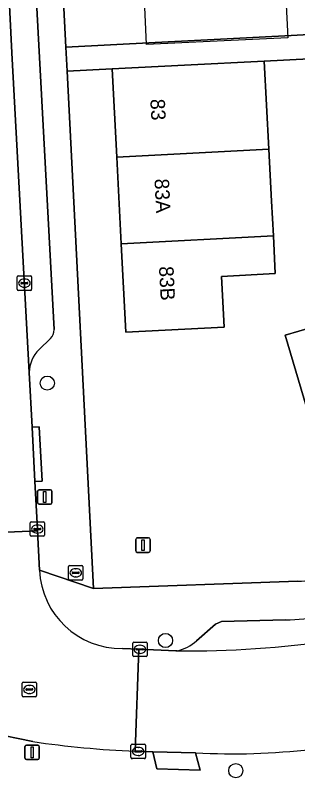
# Model space of a CAD drawing. Extents: x 158086 to 159499, y 382904 to 383981.
# Drawn here: x 158897.5 to 158917, y 383352.1 to 383404.7 of the extents above; entities that cross this region are included whole.
import ezdxf

# ---------------------------------------------------------------- set-up
doc = ezdxf.new("R2010")
doc.units = 0
for name, color, linetype in [('IMGEO_Boom', 7, 'Continuous'), ('IMGEO_Brandkraan', 7, 'Continuous'), ('IMGEO_Erf', 7, 'Continuous'), ('IMGEO_Kolk', 7, 'Continuous'), ('IMGEO_Lichtmast', 7, 'Continuous'), ('IMGEO_Pand', 7, 'Continuous'), ('IMGEO_Pand_nummerreeks', 7, 'Continuous'), ('IMGEO_Pand_vergunning_verleend', 7, 'Continuous'), ('IMGEO_Parkeervlak_open', 7, 'Continuous'), ('IMGEO_Rijbaan_lokaal_open', 7, 'Continuous'), ('IMGEO_Rioolput', 7, 'Continuous'), ('IMGEO_Voetpad_open', 7, 'Continuous')]:
    doc.layers.add(name, color=color, linetype=linetype)

msp = doc.modelspace()

# ---------------------------------------------------------------- linework, layer by layer
at = {"layer": 'IMGEO_Boom'}
for centre in [(158899.692, 383379.334), (158907.858, 383361.557), (158912.717, 383352.566)]:
    msp.add_circle(centre, 0.489, dxfattribs=at)
at = {"layer": 'IMGEO_Brandkraan'}
for p, q in [((158901.156, 383365.806), (158901.156, 383366.658)), ((158901.231, 383366.732), (158902.083, 383366.732)), ((158901.644, 383366.512), (158901.669, 383366.512)), ((158902.157, 383366.658), (158902.157, 383365.806)), ((158901.415, 383366.226), (158901.415, 383366.238)), ((158901.853, 383366.189), (158901.455, 383366.189)), ((158901.458, 383366.275), (158901.856, 383366.275)), ((158901.667, 383365.952), (158901.642, 383365.952)), ((158901.899, 383366.238), (158901.899, 383366.226)), ((158902.083, 383365.732), (158901.231, 383365.732))]:
    msp.add_line(p, q, dxfattribs=at)
for points in [[(158901.156, 383365.806), (158901.156, 383366.658)], [(158901.231, 383366.732), (158902.083, 383366.732)], [(158902.157, 383366.658), (158902.157, 383365.806)], [(158902.083, 383365.732), (158901.231, 383365.732)]]:
    msp.add_lwpolyline(points, dxfattribs=at)
for centre, radius, start, end in [((158901.233, 383366.656), 0.0765, 91.552, 178.448), ((158901.233, 383366.656), 0.0765, 91.552, 178.448), ((158902.081, 383366.656), 0.0765, 1.552, 88.448), ((158902.081, 383366.656), 0.0765, 1.552, 88.448), ((158901.455, 383366.235), 0.0403, 85.8775, 175.7526), ((158901.452, 383366.225), 0.0366, 178.938, 274.7102), ((158901.856, 383366.232), 0.043, 264.8664, 352.4533), ((158901.86, 383366.237), 0.0386, 1.7309, 96.639), ((158901.233, 383365.808), 0.0765, 181.552, 268.448), ((158901.233, 383365.808), 0.0765, 181.552, 268.448), ((158902.081, 383365.808), 0.0765, 271.552, 358.448), ((158902.081, 383365.808), 0.0765, 271.552, 358.448)]:
    msp.add_arc(centre, radius, start, end, dxfattribs=at)
for centre, major_axis, ratio, start_param, end_param in [((158901.643, 383366.232), (-0.387, 0.002), 0.722429, 4.712389, 7.853982), ((158901.668, 383366.232), (-0.39, 0.002), 0.717154, 1.570796, 4.712389)]:
    msp.add_ellipse(centre, major_axis=major_axis, ratio=ratio, start_param=start_param, end_param=end_param, dxfattribs=at)
at = {"layer": 'IMGEO_Erf'}
for points in [[(158898.201, 383456.346), (158900.97, 383402.538), (158907.136, 383402.855), (158912.13, 383403.115), (158916.543, 383403.344), (158918.608, 383403.452), (158918.596, 383403.675), (158929.519, 383404.297), (158929.403, 383404.042), (158934.745, 383404.327), (158936.388, 383404.415), (158935.294, 383408.293)], [(158921.657, 383386.888), (158922.254, 383388.21), (158922.499, 383388.752), (158920.79, 383389.524), (158921.396, 383390.834), (158918.923, 383391.978), (158920.68, 383395.777), (158922.416, 383399.528), (158924.889, 383398.384), (158926.654, 383402.198), (158914.688, 383401.579), (158915.004, 383395.482), (158915.19, 383391.89), (158915.313, 383389.503), (158915.448, 383386.896), (158911.73, 383386.703), (158911.912, 383383.192), (158905.119, 383382.841), (158904.802, 383388.957), (158904.493, 383394.936), (158904.177, 383401.035), (158901.056, 383400.874), (158902.894, 383365.138), (158916.998, 383365.647)], [(158920.898, 383366.383), (158919.749, 383370.262), (158919.247, 383370.113), (158919.167, 383370.382), (158919.671, 383370.531), (158919.007, 383372.772), (158918.485, 383372.617), (158918.393, 383372.93), (158918.956, 383373.097), (158916.131, 383382.636), (158919.916, 383383.757), (158921.657, 383386.888)]]:
    msp.add_lwpolyline(points, dxfattribs=at)
msp.add_arc((158916.222, 383380.457), 14.831, 272.9974, 288.3767, dxfattribs=at)
at = {"layer": 'IMGEO_Kolk'}
for p, q in [((158897.61, 383385.812), (158897.61, 383386.664)), ((158897.685, 383386.738), (158898.537, 383386.738)), ((158898.098, 383386.518), (158898.123, 383386.518)), ((158898.611, 383386.664), (158898.611, 383385.812)), ((158897.869, 383386.232), (158897.869, 383386.244)), ((158898.307, 383386.195), (158897.909, 383386.195)), ((158897.912, 383386.281), (158898.31, 383386.281)), ((158898.121, 383385.958), (158898.096, 383385.958)), ((158898.353, 383386.244), (158898.353, 383386.232)), ((158898.537, 383385.738), (158897.685, 383385.738)), ((158898.505, 383368.826), (158898.505, 383369.678)), ((158898.58, 383369.752), (158899.432, 383369.752)), ((158899.506, 383369.678), (158899.506, 383368.826)), ((158898.764, 383369.246), (158898.764, 383369.258)), ((158899.202, 383369.209), (158898.804, 383369.209)), ((158898.807, 383369.295), (158899.205, 383369.295)), ((158898.993, 383369.532), (158899.018, 383369.532)), ((158899.248, 383369.258), (158899.248, 383369.246)), ((158899.432, 383368.752), (158898.58, 383368.752)), ((158899.016, 383368.972), (158898.991, 383368.972)), ((158905.593, 383360.519), (158905.593, 383361.371)), ((158905.668, 383361.445), (158906.52, 383361.445)), ((158906.081, 383361.225), (158906.106, 383361.225)), ((158906.594, 383361.371), (158906.594, 383360.519)), ((158905.852, 383360.939), (158905.852, 383360.951)), ((158906.29, 383360.902), (158905.892, 383360.902)), ((158905.895, 383360.988), (158906.293, 383360.988)), ((158906.104, 383360.665), (158906.079, 383360.665)), ((158906.336, 383360.951), (158906.336, 383360.939)), ((158906.52, 383360.445), (158905.668, 383360.445)), ((158905.475, 383353.469), (158905.475, 383354.321)), ((158905.55, 383354.395), (158906.402, 383354.395)), ((158906.476, 383354.321), (158906.476, 383353.469)), ((158905.734, 383353.889), (158905.734, 383353.901)), ((158906.172, 383353.852), (158905.774, 383353.852)), ((158905.777, 383353.938), (158906.175, 383353.938)), ((158905.963, 383354.175), (158905.988, 383354.175)), ((158906.218, 383353.901), (158906.218, 383353.889)), ((158906.402, 383353.395), (158905.55, 383353.395)), ((158905.986, 383353.615), (158905.961, 383353.615))]:
    msp.add_line(p, q, dxfattribs=at)
for points in [[(158897.61, 383385.812), (158897.61, 383386.664)], [(158897.685, 383386.738), (158898.537, 383386.738)], [(158898.611, 383386.664), (158898.611, 383385.812)], [(158898.537, 383385.738), (158897.685, 383385.738)], [(158898.505, 383368.826), (158898.505, 383369.678)], [(158898.58, 383369.752), (158899.432, 383369.752)], [(158899.506, 383369.678), (158899.506, 383368.826)], [(158899.432, 383368.752), (158898.58, 383368.752)], [(158905.593, 383360.519), (158905.593, 383361.371)], [(158905.668, 383361.445), (158906.52, 383361.445)], [(158906.594, 383361.371), (158906.594, 383360.519)], [(158906.52, 383360.445), (158905.668, 383360.445)], [(158905.475, 383353.469), (158905.475, 383354.321)], [(158905.55, 383354.395), (158906.402, 383354.395)], [(158906.476, 383354.321), (158906.476, 383353.469)], [(158906.402, 383353.395), (158905.55, 383353.395)]]:
    msp.add_lwpolyline(points, dxfattribs=at)
for centre, radius, start, end in [((158897.687, 383386.662), 0.0765, 91.552, 178.448), ((158897.687, 383386.662), 0.0765, 91.552, 178.448), ((158898.535, 383386.662), 0.0765, 1.552, 88.448), ((158898.535, 383386.662), 0.0765, 1.552, 88.448), ((158897.909, 383386.241), 0.0403, 85.8775, 175.7526), ((158897.906, 383386.231), 0.0366, 178.938, 274.7102), ((158898.31, 383386.238), 0.043, 264.8664, 352.4533), ((158898.314, 383386.243), 0.0386, 1.7309, 96.639), ((158897.687, 383385.814), 0.0765, 181.552, 268.448), ((158897.687, 383385.814), 0.0765, 181.552, 268.448), ((158898.535, 383385.814), 0.0765, 271.552, 358.448), ((158898.535, 383385.814), 0.0765, 271.552, 358.448), ((158898.582, 383369.676), 0.0765, 91.552, 178.448), ((158898.582, 383369.676), 0.0765, 91.552, 178.448), ((158899.43, 383369.676), 0.0765, 1.552, 88.448), ((158899.43, 383369.676), 0.0765, 1.552, 88.448), ((158898.804, 383369.255), 0.0403, 85.8775, 175.7526), ((158898.801, 383369.245), 0.0366, 178.938, 274.7102), ((158899.205, 383369.252), 0.043, 264.8664, 352.4533), ((158899.209, 383369.257), 0.0386, 1.7309, 96.639), ((158898.582, 383368.828), 0.0765, 181.552, 268.448), ((158898.582, 383368.828), 0.0765, 181.552, 268.448), ((158899.43, 383368.828), 0.0765, 271.552, 358.448), ((158899.43, 383368.828), 0.0765, 271.552, 358.448), ((158905.67, 383361.369), 0.0765, 91.552, 178.448), ((158905.67, 383361.369), 0.0765, 91.552, 178.448), ((158906.518, 383361.369), 0.0765, 1.552, 88.448), ((158906.518, 383361.369), 0.0765, 1.552, 88.448), ((158905.892, 383360.948), 0.0403, 85.8775, 175.7526), ((158905.889, 383360.938), 0.0366, 178.938, 274.7102), ((158906.293, 383360.945), 0.043, 264.8664, 352.4533), ((158906.297, 383360.95), 0.0386, 1.7309, 96.639), ((158905.67, 383360.521), 0.0765, 181.552, 268.448), ((158905.67, 383360.521), 0.0765, 181.552, 268.448), ((158906.518, 383360.521), 0.0765, 271.552, 358.448), ((158906.518, 383360.521), 0.0765, 271.552, 358.448), ((158905.552, 383354.319), 0.0765, 91.552, 178.448), ((158905.552, 383354.319), 0.0765, 91.552, 178.448), ((158906.4, 383354.319), 0.0765, 1.552, 88.448), ((158906.4, 383354.319), 0.0765, 1.552, 88.448), ((158905.774, 383353.898), 0.0403, 85.8775, 175.7526), ((158905.771, 383353.888), 0.0366, 178.938, 274.7102), ((158906.175, 383353.895), 0.043, 264.8664, 352.4533), ((158906.179, 383353.9), 0.0386, 1.7309, 96.639), ((158905.552, 383353.471), 0.0765, 181.552, 268.448), ((158905.552, 383353.471), 0.0765, 181.552, 268.448), ((158906.4, 383353.471), 0.0765, 271.552, 358.448), ((158906.4, 383353.471), 0.0765, 271.552, 358.448)]:
    msp.add_arc(centre, radius, start, end, dxfattribs=at)
for centre, major_axis, ratio, start_param, end_param in [((158898.097, 383386.238), (-0.387, 0.002), 0.722429, 4.712389, 7.853982), ((158898.122, 383386.238), (-0.39, 0.002), 0.717154, 1.570796, 4.712389), ((158898.992, 383369.252), (-0.387, 0.002), 0.722429, 4.712389, 7.853982), ((158899.017, 383369.252), (-0.39, 0.002), 0.717154, 1.570796, 4.712389), ((158906.08, 383360.945), (-0.387, 0.002), 0.722429, 4.712389, 7.853982), ((158906.105, 383360.945), (-0.39, 0.002), 0.717154, 1.570796, 4.712389), ((158905.962, 383353.895), (-0.387, 0.002), 0.722429, 4.712389, 7.853982), ((158905.987, 383353.895), (-0.39, 0.002), 0.717154, 1.570796, 4.712389)]:
    msp.add_ellipse(centre, major_axis=major_axis, ratio=ratio, start_param=start_param, end_param=end_param, dxfattribs=at)
at = {"layer": 'IMGEO_Lichtmast'}
for p, q in [((158899.021, 383371.062), (158899.021, 383371.862)), ((158899.021, 383371.862), (158899.021, 383371.062)), ((158899.121, 383371.962), (158899.911, 383371.962)), ((158899.911, 383371.962), (158899.121, 383371.962)), ((158900.011, 383371.862), (158900.011, 383371.062)), ((158900.011, 383371.062), (158900.011, 383371.862)), ((158899.911, 383370.962), (158899.121, 383370.962)), ((158899.121, 383370.962), (158899.911, 383370.962)), ((158905.806, 383367.742), (158905.806, 383368.542)), ((158905.806, 383368.542), (158905.806, 383367.742)), ((158905.906, 383368.642), (158906.696, 383368.642)), ((158906.696, 383368.642), (158905.906, 383368.642)), ((158906.796, 383368.542), (158906.796, 383367.742)), ((158906.796, 383367.742), (158906.796, 383368.542)), ((158906.696, 383367.642), (158905.906, 383367.642)), ((158905.906, 383367.642), (158906.696, 383367.642)), ((158898.247, 383354.33), (158899.037, 383354.33)), ((158899.037, 383354.33), (158898.247, 383354.33)), ((158898.147, 383353.43), (158898.147, 383354.23)), ((158898.147, 383354.23), (158898.147, 383353.43)), ((158899.137, 383354.23), (158899.137, 383353.43)), ((158899.137, 383353.43), (158899.137, 383354.23)), ((158899.037, 383353.33), (158898.247, 383353.33)), ((158898.247, 383353.33), (158899.037, 383353.33))]:
    msp.add_line(p, q, dxfattribs=at)
for points in [[(158899.441, 383371.837), (158899.591, 383371.837), (158899.591, 383371.087), (158899.441, 383371.087), (158899.441, 383371.837)], [(158906.226, 383368.517), (158906.376, 383368.517), (158906.376, 383367.767), (158906.226, 383367.767), (158906.226, 383368.517)], [(158898.567, 383354.205), (158898.717, 383354.205), (158898.717, 383353.455), (158898.567, 383353.455), (158898.567, 383354.205)]]:
    msp.add_lwpolyline(points, dxfattribs=at)
for centre, start, end in [((158899.121, 383371.862), 90, 180), ((158899.121, 383371.862), 90, 180), ((158899.911, 383371.862), 0, 90), ((158899.911, 383371.862), 360, 90), ((158899.121, 383371.062), 180, 270), ((158899.121, 383371.062), 180, 270), ((158899.911, 383371.062), 270, 0), ((158899.911, 383371.062), 270, 0), ((158905.906, 383368.542), 90, 180), ((158905.906, 383368.542), 90, 180), ((158906.696, 383368.542), 0, 90), ((158906.696, 383368.542), 360, 90), ((158905.906, 383367.742), 180, 270), ((158905.906, 383367.742), 180, 270), ((158906.696, 383367.742), 270, 0), ((158906.696, 383367.742), 270, 0), ((158898.247, 383354.23), 90, 180), ((158898.247, 383354.23), 90, 180), ((158899.037, 383354.23), 0, 90), ((158899.037, 383354.23), 360, 90), ((158898.247, 383353.43), 180, 270), ((158898.247, 383353.43), 180, 270), ((158899.037, 383353.43), 270, 0), ((158899.037, 383353.43), 270, 0)]:
    msp.add_arc(centre, 0.1, start, end, dxfattribs=at)
at = {"layer": 'IMGEO_Pand'}
for points in [[(158904.493, 383394.936), (158915.004, 383395.482), (158914.688, 383401.579), (158909.162, 383401.293), (158904.177, 383401.035)], [(158915.313, 383389.503), (158915.19, 383391.89), (158915.004, 383395.482), (158904.493, 383394.936), (158904.802, 383388.957)], [(158939.766, 383392.44), (158934.986, 383390.975), (158921.657, 383386.888), (158919.916, 383383.757), (158916.131, 383382.636), (158918.956, 383373.097), (158918.393, 383372.93), (158918.485, 383372.617), (158919.007, 383372.772), (158919.671, 383370.531), (158919.167, 383370.382), (158919.247, 383370.113), (158919.749, 383370.262), (158920.898, 383366.383), (158925.931, 383367.872), (158924.06, 383374.095), (158943.494, 383379.853)], [(158904.802, 383388.957), (158905.119, 383382.841), (158911.912, 383383.192), (158911.73, 383386.703), (158915.448, 383386.896), (158915.313, 383389.503)]]:
    msp.add_lwpolyline(points, close=True, dxfattribs=at)
at = {"layer": 'IMGEO_Pand_vergunning_verleend'}
msp.add_lwpolyline([(158906.381, 383406.352), (158916.139, 383406.819), (158916.313, 383403.178), (158906.555, 383402.711)], close=True, dxfattribs=at)
at = {"layer": 'IMGEO_Parkeervlak_open'}
for points in [[(158895.987, 383427.119), (158896.019, 383426.484), (158897.244, 383402.134), (158898.446, 383380.066)], [(158900.162, 383383.031), (158897.941, 383424.478)], [(158899.123, 383381.647), (158899.918, 383382.412)], [(158916.147, 383362.975), (158911.739, 383362.869), (158911.306, 383362.693), (158909.999, 383361.529)]]:
    msp.add_lwpolyline(points, dxfattribs=at)
for centre, radius, start, end in [((158899.359, 383382.99), 0.804, 314.046, 2.9269), ((158900.637, 383380.063), 2.191, 133.7082, 179.9296), ((158915.09, 383389.2), 26.247, 272.3077, 283.4634), ((158909.461, 383431.031), 70.191, 269.359, 278.193), ((158908.013, 383363.749), 2.978, 282.8605, 311.8181)]:
    msp.add_arc(centre, radius, start, end, dxfattribs=at)
at = {"layer": 'IMGEO_Rijbaan_lokaal_open'}
msp.add_lwpolyline([(158894.456, 383373.735), (158894.699, 383369.809), (158894.706, 383369.689), (158894.713, 383369.482), (158894.744, 383368.957), (158899.011, 383369.142), (158899.005, 383369.252), (158898.835, 383372.537), (158898.642, 383376.28), (158898.446, 383380.066), (158897.244, 383402.134), (158896.019, 383426.484), (158891.628, 383426.244), (158893.053, 383400.112), (158893.604, 383390.635), (158894.26, 383378.492)], close=True, dxfattribs=at)
for points in [[(158899.156, 383366.41), (158899.011, 383369.142), (158894.744, 383368.957), (158894.787, 383368.227)], [(158889.178, 383364.324), (158888.47, 383364.499), (158886.403, 383357.857), (158895.754, 383355.173), (158898.685, 383354.576)], [(158905.763, 383353.903), (158906.023, 383360.961), (158904.879, 383361.012)], [(158908.676, 383360.845), (158908.574, 383360.846), (158906.023, 383360.961), (158905.763, 383353.903), (158906.99, 383353.872), (158909.932, 383353.802)]]:
    msp.add_lwpolyline(points, dxfattribs=at)
for centre, radius, start, end in [((158904.78, 383366.64), 5.629, 182.3391, 271.0087), ((158909.461, 383431.031), 70.191, 269.359, 278.193), ((158912.536, 383400.116), 46.387, 266.7816, 286.6469), ((158909.027, 383425.789), 71.96, 261.73679, 267.40012)]:
    msp.add_arc(centre, radius, start, end, dxfattribs=at)
at = {"layer": 'IMGEO_Rioolput'}
for p, q in [((158897.953, 383357.75), (158897.953, 383358.602)), ((158898.028, 383358.676), (158898.88, 383358.676)), ((158898.954, 383358.602), (158898.954, 383357.75)), ((158898.212, 383358.17), (158898.212, 383358.182)), ((158898.65, 383358.133), (158898.252, 383358.133)), ((158898.255, 383358.219), (158898.653, 383358.219)), ((158898.441, 383358.456), (158898.466, 383358.456)), ((158898.696, 383358.182), (158898.696, 383358.17)), ((158898.88, 383357.676), (158898.028, 383357.676)), ((158898.464, 383357.896), (158898.439, 383357.896))]:
    msp.add_line(p, q, dxfattribs=at)
for points in [[(158897.953, 383357.75), (158897.953, 383358.602)], [(158898.028, 383358.676), (158898.88, 383358.676)], [(158898.954, 383358.602), (158898.954, 383357.75)], [(158898.88, 383357.676), (158898.028, 383357.676)]]:
    msp.add_lwpolyline(points, dxfattribs=at)
for centre, radius, start, end in [((158898.03, 383358.6), 0.0765, 91.552, 178.448), ((158898.03, 383358.6), 0.0765, 91.552, 178.448), ((158898.878, 383358.6), 0.0765, 1.552, 88.448), ((158898.878, 383358.6), 0.0765, 1.552, 88.448), ((158898.252, 383358.179), 0.0403, 85.8775, 175.7526), ((158898.249, 383358.169), 0.0366, 178.938, 274.7102), ((158898.653, 383358.176), 0.043, 264.8664, 352.4533), ((158898.657, 383358.181), 0.0386, 1.7309, 96.639), ((158898.03, 383357.752), 0.0765, 181.552, 268.448), ((158898.03, 383357.752), 0.0765, 181.552, 268.448), ((158898.878, 383357.752), 0.0765, 271.552, 358.448), ((158898.878, 383357.752), 0.0765, 271.552, 358.448)]:
    msp.add_arc(centre, radius, start, end, dxfattribs=at)
for centre, major_axis, ratio, start_param, end_param in [((158898.44, 383358.176), (-0.387, 0.002), 0.722429, 4.712389, 7.853982), ((158898.465, 383358.176), (-0.39, 0.002), 0.717154, 1.570796, 4.712389)]:
    msp.add_ellipse(centre, major_axis=major_axis, ratio=ratio, start_param=start_param, end_param=end_param, dxfattribs=at)
at = {"layer": 'IMGEO_Voetpad_open'}
for points in [[(158901.056, 383400.874), (158900.97, 383402.538), (158898.201, 383456.346), (158898.118, 383457.958), (158896.02, 383498.745), (158895.992, 383499.286), (158895.955, 383500), (158895.951, 383500.075), (158895.929, 383500.485), (158893.243, 383551.098), (158893.141, 383553.024), (158891.977, 383574.95), (158891.907, 383576.278), (158889.705, 383617.76), (158889.594, 383619.86), (158888.293, 383644.38), (158885.014, 383644.62)], [(158897.941, 383424.478), (158900.162, 383383.031)], [(158898.446, 383380.066), (158898.642, 383376.28), (158899.137, 383376.309), (158899.327, 383372.566), (158898.835, 383372.537), (158899.005, 383369.252), (158899.011, 383369.142), (158899.156, 383366.41), (158902.894, 383365.138), (158901.056, 383400.874)], [(158898.685, 383354.576), (158895.754, 383355.173), (158886.403, 383357.857), (158886.223, 383357.899), (158880.188, 383359.604), (158859.089, 383365.589), (158858.805, 383364.588), (158855.625, 383365.49), (158855.909, 383366.491), (158854.716, 383366.83), (158854.432, 383365.829), (158851.092, 383366.776), (158851.376, 383367.777), (158848.856, 383368.492), (158836.657, 383371.953), (158830.616, 383373.672), (158830.515, 383373.709), (158811.299, 383379.137), (158810.816, 383379.277), (158803.832, 383381.26), (158764.081, 383392.596), (158757.401, 383394.452), (158756.229, 383394.782), (158753.608, 383395.531)], [(158899.918, 383382.412), (158899.123, 383381.647)], [(158916.998, 383365.647), (158902.894, 383365.138), (158899.156, 383366.41)], [(158909.999, 383361.529), (158911.306, 383362.693), (158911.739, 383362.869), (158916.147, 383362.975)], [(158904.879, 383361.012), (158906.023, 383360.961), (158908.574, 383360.846), (158908.676, 383360.845)], [(158909.932, 383353.802), (158910.251, 383352.602), (158907.269, 383352.698), (158906.99, 383353.872), (158905.763, 383353.903)]]:
    msp.add_lwpolyline(points, dxfattribs=at)
for points in [[(158928.934, 383403.005), (158929.403, 383404.042), (158929.519, 383404.297), (158918.596, 383403.675), (158918.608, 383403.452), (158916.543, 383403.344), (158912.13, 383403.115), (158907.136, 383402.855), (158900.97, 383402.538), (158901.056, 383400.874), (158904.177, 383401.035), (158909.162, 383401.293), (158914.688, 383401.579), (158926.654, 383402.198), (158924.889, 383398.384), (158923.143, 383394.61), (158921.396, 383390.834), (158920.79, 383389.524), (158922.499, 383388.752)], [(158898.835, 383372.537), (158899.327, 383372.566), (158899.137, 383376.309), (158898.642, 383376.28)], [(158906.99, 383353.872), (158907.269, 383352.698), (158910.251, 383352.602), (158909.932, 383353.802)]]:
    msp.add_lwpolyline(points, close=True, dxfattribs=at)
for centre, radius, start, end in [((158899.359, 383382.99), 0.804, 314.046, 2.9269), ((158900.637, 383380.063), 2.191, 133.7082, 179.9296), ((158904.78, 383366.64), 5.629, 182.3391, 271.0087), ((158916.222, 383380.457), 14.831, 272.9974, 288.3767), ((158915.09, 383389.2), 26.247, 272.3077, 283.4634), ((158908.013, 383363.749), 2.978, 282.8605, 311.8181), ((158912.536, 383400.116), 46.387, 266.7816, 286.6469), ((158909.027, 383425.789), 71.96, 261.73679, 267.40012)]:
    msp.add_arc(centre, radius, start, end, dxfattribs=at)

# ---------------------------------------------------------------- texts
at = {"layer": 'IMGEO_Pand_nummerreeks'}
for s, rotation, p in [('83', 272.9639, (158906.809, 383398.941)), ('83A', 272.9701, (158907.094, 383393.432)), ('83B', 272.9671, (158907.407, 383387.384))]:
    msp.add_text(s, height=1, rotation=rotation, dxfattribs=at).set_placement(p)

doc.saveas('drawing.dxf')
